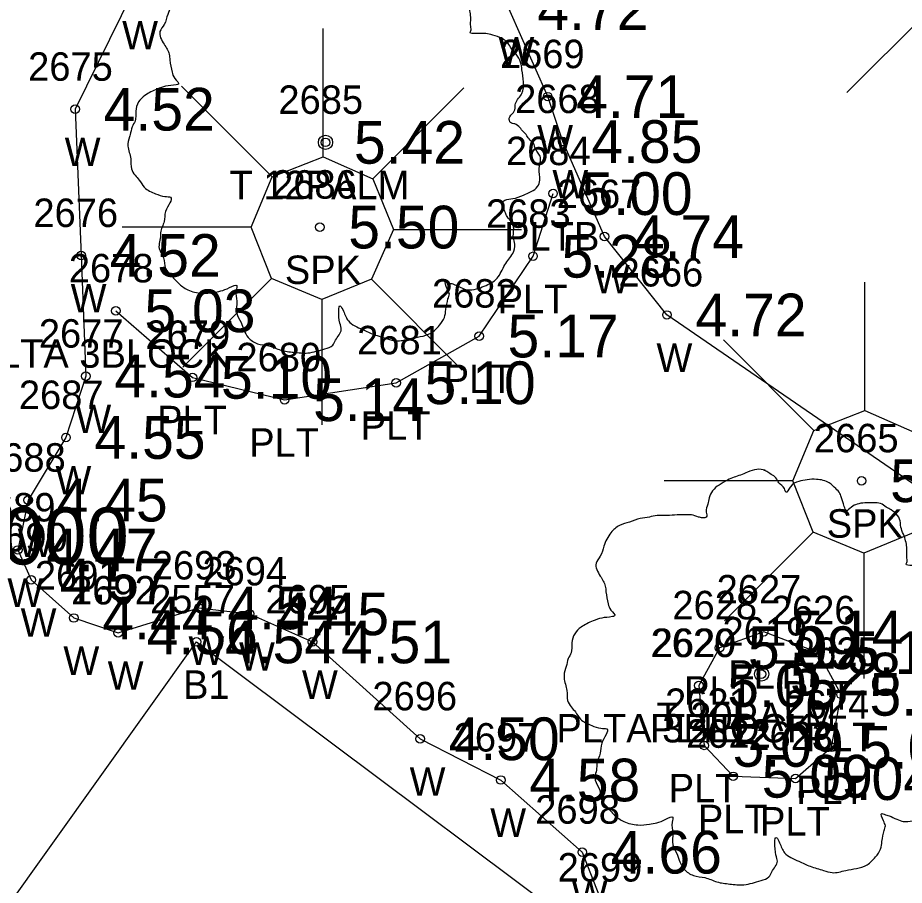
# Model space of a CAD drawing. Extents: x 2608598 to 2610682, y 641451 to 643526.
# Drawn here: x 2610088.05 to 2610119.19, y 642060.19 to 642090.67 of the extents above; entities that cross this region are included whole.
import ezdxf

# ---------------------------------------------------------------- set-up
doc = ezdxf.new("R2010")
doc.units = 0
for name, color, linetype in [('RD_EX_Bldg', 7, 'Continuous'), ('RD_EX_Bldg_txCode', 7, 'Continuous'), ('RD_EX_BldgApp', 7, 'Continuous'), ('RD_EX_BldgApp_txCode', 7, 'Continuous'), ('RD_EX_Misc_txCode', 7, 'Continuous'), ('RD_EX_TX_Bldg_ELEV', 7, 'Continuous'), ('RD_EX_TX_BldgApp_ELEV', 7, 'Continuous'), ('RD_EX_TX_Misc_ELEV', 7, 'Continuous'), ('RD_EX_TX_VEG_ELEV', 7, 'Continuous'), ('RD_EX_VEG', 7, 'Continuous'), ('RD_EX_VEG_txCode', 7, 'Continuous'), ('RD_SMD_Locator', 7, 'Continuous'), ('RD_TX_Pipe_ElevEX', 7, 'Continuous')]:
    doc.layers.add(name, color=color, linetype=linetype)

msp = doc.modelspace()

# ---------------------------------------------------------------- linework, layer by layer
at = {"layer": 'RD_EX_Bldg'}
msp.add_lwpolyline([(2610053.59, 642011.651), (2610094.327, 642068.736), (2610111.856, 642055.619), (2610105.498, 642045.99), (2610112.03, 642040.97), (2610078.047, 641993.35), (2610053.59, 642011.651)], dxfattribs=at)
at = {"layer": 'RD_EX_BldgApp'}
for p, q in [((2610120.291, 642091.155), (2610117.173, 642088.038)), ((2610098.773, 642085.777), (2610098.773, 642090.286)), ((2610096.986, 642085.079), (2610093.803, 642088.261)), ((2610100.524, 642085.007), (2610103.72, 642088.203)), ((2610096.243, 642083.315), (2610091.72, 642083.315)), ((2610101.248, 642083.233), (2610105.745, 642083.233)), ((2610096.961, 642081.503), (2610093.844, 642078.385)), ((2610100.47, 642081.478), (2610103.662, 642078.287)), ((2610117.809, 642076.863), (2610117.809, 642081.373)), ((2610098.732, 642080.771), (2610098.732, 642076.361)), ((2610116.021, 642076.165), (2610112.838, 642079.348)), ((2610115.278, 642074.401), (2610110.756, 642074.401)), ((2610115.997, 642072.589), (2610112.879, 642069.472)), ((2610117.768, 642071.858), (2610117.768, 642067.447))]:
    msp.add_line(p, q, dxfattribs=at)
for points in [[(2610092.084, 642091.554), (2610090.066, 642087.454), (2610090.275, 642082.315), (2610090.442, 642078.076), (2610089.742, 642075.92), (2610088.411, 642073.718), (2610088.053, 642071.968), (2610088.518, 642070.915), (2610090.02, 642069.577), (2610091.576, 642069.053), (2610094.413, 642069.93), (2610096.189, 642069.722), (2610098.402, 642068.736), (2610102.184, 642065.332), (2610105.016, 642063.884), (2610107.881, 642061.348), (2610108.669, 642059.316), (2610108.72, 642058.165)], [(2610119.539, 642032.985), (2610125.556, 642041.329), (2610129.153, 642046.176), (2610131.221, 642048.284), (2610137.373, 642056.194), (2610138.092, 642057.602), (2610137.208, 642060.569), (2610134.6, 642063.19), (2610131.718, 642064.679), (2610129.964, 642065.077), (2610125.881, 642067.984), (2610120.868, 642073.349), (2610110.856, 642080.224), (2610108.66, 642082.981), (2610107.198, 642086.318), (2610106.665, 642087.897), (2610105.304, 642090.989)], [(2610091.496, 642080.37), (2610094.188, 642078.032), (2610097.423, 642077.245), (2610101.34, 642077.842), (2610104.255, 642079.483), (2610106.151, 642082.287), (2610106.853, 642084.489)], [(2610111.973, 642067.204), (2610112.16, 642065.1), (2610113.185, 642064.015), (2610115.368, 642063.934), (2610116.64, 642065.037), (2610116.97, 642066.894), (2610116.18, 642068.357), (2610114.255, 642069.088), (2610112.7, 642068.531), (2610111.973, 642067.204)]]:
    msp.add_lwpolyline(points, dxfattribs=at)
for points in [[(2610096.986, 642085.079), (2610098.773, 642085.777), (2610100.524, 642085.007), (2610101.248, 642083.233), (2610100.47, 642081.478), (2610098.732, 642080.771), (2610096.961, 642081.503), (2610096.243, 642083.315)], [(2610116.021, 642076.165), (2610117.809, 642076.863), (2610119.559, 642076.094), (2610120.284, 642074.319), (2610119.506, 642072.565), (2610117.768, 642071.858), (2610115.997, 642072.589), (2610115.278, 642074.401)]]:
    msp.add_lwpolyline(points, close=True, dxfattribs=at)
at = {"layer": 'RD_EX_VEG'}
for centre, radius in [((2610098.858, 642086.29), 0.25), ((2610098.845, 642086.271), 0.0001), ((2610114.179, 642067.606), 0.25), ((2610114.166, 642067.587), 0.0001)]:
    msp.add_circle(centre, radius, dxfattribs=at)
for points in [[(2610098.989, 642093.457), (2610098.69, 642093.482), (2610098.365, 642093.382), (2610098.115, 642093.282), (2610097.89, 642093.207), (2610097.665, 642093.107), (2610097.365, 642092.933), (2610097.14, 642092.733), (2610097.015, 642092.483), (2610096.965, 642092.258), (2610096.915, 642091.983), (2610096.915, 642091.808), (2610096.79, 642091.783), (2610096.64, 642091.808), (2610096.391, 642091.883), (2610096.141, 642091.883), (2610095.891, 642091.883), (2610095.541, 642091.858), (2610095.191, 642091.858), (2610094.916, 642091.808), (2610094.591, 642091.758), (2610094.217, 642091.633), (2610093.867, 642091.508), (2610093.567, 642091.258), (2610093.317, 642090.784), (2610093.192, 642090.434), (2610093.042, 642090.184), (2610093.192, 642089.734), (2610093.367, 642089.384), (2610093.392, 642089.184), (2610093.467, 642088.759), (2610093.567, 642088.535), (2610093.692, 642088.335), (2610093.617, 642088.31), (2610093.242, 642088.26), (2610092.942, 642088.16), (2610092.517, 642087.935), (2610092.292, 642087.71), (2610092.192, 642087.385), (2610092.167, 642087.035), (2610092.068, 642086.835), (2610091.993, 642086.56), (2610091.968, 642086.485), (2610091.918, 642086.161), (2610092.018, 642085.711), (2610092.043, 642085.361), (2610092.167, 642085.136), (2610092.317, 642084.961), (2610092.492, 642084.711), (2610092.892, 642084.486), (2610093.217, 642084.386), (2610093.417, 642084.361), (2610093.242, 642083.862), (2610093.192, 642083.512), (2610093.067, 642083.112), (2610093.067, 642083.037), (2610093.017, 642082.562), (2610093.167, 642082.237), (2610093.242, 642081.862), (2610093.417, 642081.638), (2610093.692, 642081.338), (2610094.017, 642081.113), (2610094.516, 642080.988), (2610094.916, 642081.013), (2610095.491, 642081.188), (2610095.741, 642081.263), (2610095.716, 642081.088), (2610095.741, 642080.713), (2610095.741, 642080.288), (2610095.891, 642079.963), (2610095.991, 642079.688), (2610096.141, 642079.438), (2610096.466, 642079.214), (2610096.865, 642079.139), (2610097.29, 642078.989), (2610097.74, 642078.914), (2610098.24, 642078.889), (2610098.84, 642079.039), (2610099.114, 642079.164), (2610099.214, 642079.339), (2610099.414, 642079.713), (2610099.364, 642079.938), (2610099.389, 642080.538), (2610099.489, 642080.363), (2610099.664, 642080.013), (2610100.164, 642079.713), (2610100.564, 642079.538), (2610101.039, 642079.388), (2610101.338, 642079.314), (2610101.813, 642079.388), (2610102.188, 642079.463), (2610102.563, 642079.588), (2610102.863, 642079.863), (2610103.038, 642080.138), (2610103.088, 642080.413), (2610103.163, 642080.788), (2610103.213, 642080.963)], [(2610103.213, 642080.963), (2610103.138, 642081.138), (2610103.088, 642081.388), (2610103.163, 642081.363), (2610103.338, 642081.313), (2610103.612, 642081.188), (2610103.837, 642081.113), (2610104.162, 642081.138), (2610104.437, 642081.238), (2610104.887, 642081.513), (2610105.162, 642081.987), (2610105.437, 642082.387), (2610105.512, 642082.712), (2610105.462, 642082.937), (2610105.437, 642083.437), (2610105.237, 642083.687), (2610105.187, 642083.812), (2610105.087, 642084.211), (2610105.162, 642084.261), (2610105.437, 642084.311), (2610105.811, 642084.436), (2610106.086, 642084.561), (2610106.311, 642084.736), (2610106.386, 642084.961), (2610106.361, 642085.361), (2610106.411, 642085.761), (2610106.336, 642085.911), (2610106.236, 642086.061), (2610106.161, 642086.261), (2610106.011, 642086.41), (2610105.911, 642086.56), (2610105.811, 642086.66), (2610105.687, 642086.81), (2610105.512, 642086.935), (2610105.362, 642086.985), (2610105.312, 642087.135), (2610105.462, 642087.335), (2610105.512, 642087.435), (2610105.537, 642087.66), (2610105.762, 642088.01), (2610105.811, 642088.41), (2610105.762, 642088.834), (2610105.712, 642089.109), (2610105.562, 642089.384), (2610105.362, 642089.634), (2610105.237, 642089.809), (2610105.062, 642089.934), (2610104.737, 642090.059), (2610104.487, 642090.109), (2610104.137, 642090.109), (2610103.937, 642090.159), (2610103.962, 642090.209), (2610103.962, 642090.359), (2610103.962, 642090.634), (2610103.887, 642091.083), (2610103.737, 642091.583), (2610103.737, 642091.608), (2610103.637, 642091.858), (2610103.413, 642092.058), (2610103.238, 642092.158), (2610103.038, 642092.283), (2610102.788, 642092.308), (2610102.488, 642092.308), (2610102.213, 642092.258), (2610102.013, 642092.158), (2610101.838, 642092.033), (2610101.763, 642092.183), (2610101.663, 642092.483), (2610101.613, 642092.633), (2610101.463, 642092.808), (2610101.239, 642093.008), (2610100.789, 642093.132), (2610100.164, 642093.058), (2610099.864, 642092.858), (2610099.714, 642092.683), (2610099.664, 642092.808), (2610099.464, 642093.008), (2610099.364, 642093.182), (2610099.189, 642093.307), (2610099.039, 642093.407), (2610098.939, 642093.457)], [(2610114.311, 642074.773), (2610114.011, 642074.798), (2610113.686, 642074.698), (2610113.436, 642074.598), (2610113.211, 642074.523), (2610112.986, 642074.423), (2610112.686, 642074.248), (2610112.461, 642074.048), (2610112.336, 642073.799), (2610112.286, 642073.574), (2610112.237, 642073.299), (2610112.237, 642073.124), (2610112.112, 642073.099), (2610111.962, 642073.124), (2610111.712, 642073.199), (2610111.462, 642073.199), (2610111.212, 642073.199), (2610110.862, 642073.174), (2610110.512, 642073.174), (2610110.237, 642073.124), (2610109.913, 642073.074), (2610109.538, 642072.949), (2610109.188, 642072.824), (2610108.888, 642072.574), (2610108.638, 642072.099), (2610108.513, 642071.749), (2610108.363, 642071.5), (2610108.513, 642071.05), (2610108.688, 642070.7), (2610108.713, 642070.5), (2610108.788, 642070.075), (2610108.888, 642069.85), (2610109.013, 642069.65), (2610108.938, 642069.625), (2610108.563, 642069.575), (2610108.263, 642069.475), (2610107.838, 642069.251), (2610107.614, 642069.026), (2610107.514, 642068.701), (2610107.489, 642068.351), (2610107.389, 642068.151), (2610107.314, 642067.876), (2610107.289, 642067.801), (2610107.239, 642067.476), (2610107.339, 642067.026), (2610107.364, 642066.677), (2610107.489, 642066.452), (2610107.639, 642066.277), (2610107.813, 642066.027), (2610108.213, 642065.802), (2610108.538, 642065.702), (2610108.738, 642065.677), (2610108.563, 642065.177), (2610108.513, 642064.827), (2610108.388, 642064.428), (2610108.388, 642064.353), (2610108.338, 642063.878), (2610108.488, 642063.553), (2610108.563, 642063.178), (2610108.738, 642062.953), (2610109.013, 642062.653), (2610109.338, 642062.429), (2610109.838, 642062.304), (2610110.237, 642062.329), (2610110.812, 642062.503), (2610111.062, 642062.578), (2610111.037, 642062.404), (2610111.062, 642062.029), (2610111.062, 642061.604), (2610111.212, 642061.279), (2610111.312, 642061.004), (2610111.462, 642060.754), (2610111.787, 642060.529), (2610112.187, 642060.454), (2610112.611, 642060.304), (2610113.061, 642060.229), (2610113.561, 642060.204), (2610114.161, 642060.354), (2610114.436, 642060.479), (2610114.536, 642060.654), (2610114.735, 642061.029), (2610114.685, 642061.254), (2610114.71, 642061.854), (2610114.81, 642061.679), (2610114.985, 642061.329), (2610115.485, 642061.029), (2610115.885, 642060.854), (2610116.36, 642060.704), (2610116.66, 642060.629), (2610117.134, 642060.704), (2610117.509, 642060.779), (2610117.884, 642060.904), (2610118.184, 642061.179), (2610118.359, 642061.454), (2610118.409, 642061.729), (2610118.484, 642062.104), (2610118.534, 642062.279)], [(2610118.534, 642062.279), (2610118.459, 642062.454), (2610118.409, 642062.703), (2610118.484, 642062.678), (2610118.659, 642062.628), (2610118.934, 642062.503), (2610119.159, 642062.429), (2610119.483, 642062.454), (2610119.758, 642062.553), (2610120.208, 642062.828), (2610120.483, 642063.303), (2610120.758, 642063.703), (2610120.833, 642064.028), (2610120.783, 642064.253), (2610120.758, 642064.752), (2610120.558, 642065.002), (2610120.508, 642065.127), (2610120.408, 642065.527), (2610120.483, 642065.577), (2610120.758, 642065.627), (2610121.133, 642065.752), (2610121.408, 642065.877), (2610121.632, 642066.052), (2610121.707, 642066.277), (2610121.682, 642066.677), (2610121.732, 642067.076), (2610121.657, 642067.226), (2610121.557, 642067.376), (2610121.482, 642067.576), (2610121.333, 642067.726), (2610121.233, 642067.876), (2610121.133, 642067.976), (2610121.008, 642068.126), (2610120.833, 642068.251), (2610120.683, 642068.301), (2610120.633, 642068.451), (2610120.783, 642068.651), (2610120.833, 642068.751), (2610120.858, 642068.976), (2610121.083, 642069.325), (2610121.133, 642069.725), (2610121.083, 642070.15), (2610121.033, 642070.425), (2610120.883, 642070.7), (2610120.683, 642070.95), (2610120.558, 642071.125), (2610120.383, 642071.25), (2610120.058, 642071.375), (2610119.808, 642071.425), (2610119.458, 642071.425), (2610119.258, 642071.475), (2610119.283, 642071.525), (2610119.283, 642071.674), (2610119.283, 642071.949), (2610119.208, 642072.399), (2610119.059, 642072.899), (2610119.059, 642072.924), (2610118.959, 642073.174), (2610118.734, 642073.374), (2610118.559, 642073.474), (2610118.359, 642073.599), (2610118.109, 642073.624), (2610117.809, 642073.624), (2610117.534, 642073.574), (2610117.334, 642073.474), (2610117.159, 642073.349), (2610117.084, 642073.499), (2610116.984, 642073.799), (2610116.934, 642073.948), (2610116.785, 642074.123), (2610116.56, 642074.323), (2610116.11, 642074.448), (2610115.485, 642074.373), (2610115.185, 642074.173), (2610115.035, 642073.998), (2610114.985, 642074.123), (2610114.785, 642074.323), (2610114.685, 642074.498), (2610114.511, 642074.623), (2610114.361, 642074.723), (2610114.261, 642074.773)]]:
    msp.add_spline(points, degree=3, dxfattribs=at)
at = {"layer": 'RD_SMD_Locator'}
for centre in [(2610106.665, 642087.897), (2610090.066, 642087.454), (2610098.858, 642086.29), (2610107.198, 642086.318), (2610106.853, 642084.489), (2610098.659, 642083.312), (2610108.66, 642082.981), (2610090.275, 642082.315), (2610106.151, 642082.287), (2610091.496, 642080.37), (2610110.856, 642080.224), (2610104.255, 642079.483), (2610090.442, 642078.076), (2610094.188, 642078.032), (2610101.34, 642077.842), (2610097.423, 642077.245), (2610089.742, 642075.92), (2610117.695, 642074.399), (2610088.411, 642073.718), (2610088.053, 642071.968), (2610088.518, 642070.915), (2610094.413, 642069.93), (2610096.189, 642069.722), (2610090.02, 642069.577), (2610114.255, 642069.088), (2610091.576, 642069.053), (2610094.327, 642068.736), (2610098.402, 642068.736), (2610112.7, 642068.531), (2610116.18, 642068.357), (2610114.179, 642067.606), (2610111.973, 642067.204), (2610111.973, 642067.204), (2610116.97, 642066.894), (2610102.184, 642065.332), (2610112.16, 642065.1), (2610116.64, 642065.037), (2610105.016, 642063.884), (2610113.185, 642064.015), (2610115.368, 642063.934), (2610107.881, 642061.348)]:
    msp.add_circle(centre, 0.15, dxfattribs=at)

# ---------------------------------------------------------------- texts
at = {"layer": 'RD_EX_Bldg_txCode'}
for s, p in [('2557', (2610092.697, 642069.736)), ('B1', (2610093.855, 642066.736))]:
    msp.add_text(s, height=1, dxfattribs=at).set_placement(p)
at = {"layer": 'RD_EX_BldgApp_txCode'}
for s, p in [('2684', (2610105.2, 642085.489)), ('2686', (2610096.982, 642084.312)), ('2683', (2610104.497, 642083.287)), ('PLTB', (2610105.137, 642082.489)), ('2678', (2610089.842, 642081.37)), ('SPK', (2610097.431, 642081.312)), ('2682', (2610102.601, 642080.483)), ('PLT', (2610104.907, 642080.287)), ('2679', (2610092.534, 642079.032)), ('2681', (2610099.97, 642078.842)), ('PLTA 3BLOCK', (2610086.496, 642078.37)), ('2680', (2610095.73, 642078.245)), ('PLT', (2610103.011, 642077.483)), ('PLT', (2610092.943, 642076.032)), ('PLT', (2610100.096, 642075.842)), ('2665', (2610116.018, 642075.399)), ('PLT', (2610096.179, 642075.245)), ('SPK', (2610116.467, 642072.399)), ('2627', (2610112.601, 642070.088)), ('2628', (2610111.046, 642069.531)), ('2626', (2610114.503, 642069.357)), ('2620', (2610110.28, 642068.204)), ('2629', (2610110.319, 642068.204)), ('2625', (2610115.317, 642067.894)), ('PLT', (2610113.011, 642067.088)), ('PLT', (2610111.455, 642066.531)), ('PLT', (2610114.936, 642066.357)), ('2621', (2610110.79, 642066.1)), ('2624', (2610114.986, 642066.037)), ('PLTA 3BLOCK', (2610106.973, 642065.204)), ('PLTB', (2610110.256, 642065.204)), ('2622', (2610111.532, 642065.015)), ('2623', (2610113.714, 642064.934)), ('PLT', (2610115.726, 642064.894)), ('PLT', (2610110.916, 642063.1)), ('PLT', (2610115.396, 642063.037)), ('PLT', (2610111.941, 642062.015)), ('PLT', (2610114.124, 642061.934))]:
    msp.add_text(s, height=1, dxfattribs=at).set_placement(p)
at = {"layer": 'RD_EX_Misc_txCode'}
for s, p in [('W', (2610091.714, 642089.554)), ('W', (2610104.934, 642088.989)), ('2669', (2610104.988, 642088.897)), ('2675', (2610088.412, 642088.454)), ('2668', (2610105.521, 642087.318)), ('W', (2610106.295, 642085.897)), ('W', (2610089.696, 642085.454)), ('W', (2610106.828, 642084.318)), ('2667', (2610106.982, 642083.981)), ('2676', (2610088.598, 642083.315)), ('2666', (2610109.155, 642081.224)), ('W', (2610108.289, 642080.981)), ('W', (2610089.905, 642080.315)), ('2677', (2610088.789, 642079.076)), ('W', (2610110.486, 642078.224)), ('2687', (2610088.088, 642076.92)), ('W', (2610090.072, 642076.076)), ('2688', (2610086.758, 642074.718)), ('W', (2610089.372, 642073.92)), ('2689', (2610086.399, 642072.968)), ('2690', (2610086.825, 642071.915)), ('W', (2610088.041, 642071.718)), ('2693', (2610092.759, 642070.93)), ('2694', (2610094.536, 642070.722)), ('2691', (2610088.65, 642070.577)), ('W', (2610087.682, 642069.968)), ('2692', (2610089.922, 642070.053)), ('2695', (2610096.748, 642069.736)), ('W', (2610088.148, 642068.915)), ('W', (2610094.043, 642067.93)), ('W', (2610095.819, 642067.722)), ('W', (2610089.65, 642067.577)), ('W', (2610091.206, 642067.053)), ('W', (2610098.031, 642066.736)), ('2696', (2610100.507, 642066.332)), ('2697', (2610103.362, 642064.884)), ('W', (2610101.814, 642063.332)), ('2698', (2610106.228, 642062.348)), ('W', (2610104.646, 642061.884)), ('2699', (2610107.016, 642060.316)), ('W', (2610107.511, 642059.348))]:
    msp.add_text(s, height=1, dxfattribs=at).set_placement(p)
at = {"layer": 'RD_EX_TX_Bldg_ELEV'}
msp.add_text('4.54', height=1.5, dxfattribs=at).set_placement((2610095.327, 642067.986))
at = {"layer": 'RD_EX_TX_BldgApp_ELEV'}
for s, p in [('5.00', (2610107.853, 642083.739)), ('5.50', (2610099.659, 642082.562)), ('5.28', (2610107.151, 642081.537)), ('5.03', (2610092.496, 642079.62)), ('5.17', (2610105.255, 642078.733)), ('5.10', (2610095.188, 642077.282)), ('5.10', (2610102.34, 642077.092)), ('5.14', (2610098.423, 642076.495)), ('5.32', (2610118.695, 642073.649)), ('5.14', (2610115.255, 642068.338)), ('5.09', (2610113.7, 642067.781)), ('5.14', (2610117.18, 642067.607)), ('5.05', (2610112.973, 642066.454)), ('5.05', (2610112.973, 642066.454)), ('5.11', (2610117.97, 642066.144)), ('5.09', (2610113.16, 642064.35)), ('5.02', (2610117.64, 642064.287)), ('5.09', (2610114.185, 642063.265)), ('5.04', (2610116.368, 642063.184))]:
    msp.add_text(s, height=1.5, dxfattribs=at).set_placement(p)
at = {"layer": 'RD_EX_TX_Misc_ELEV'}
for s, p in [('4.72', (2610106.304, 642090.239)), ('4.71', (2610107.665, 642087.147)), ('4.52', (2610091.066, 642086.704)), ('4.85', (2610108.198, 642085.568)), ('4.74', (2610109.66, 642082.231)), ('4.52', (2610091.275, 642081.565)), ('4.72', (2610111.856, 642079.474)), ('4.54', (2610091.442, 642077.326)), ('4.55', (2610090.742, 642075.17)), ('4.45', (2610089.411, 642072.968)), ('4.47', (2610089.053, 642071.218)), ('4.57', (2610089.518, 642070.165)), ('4.54', (2610095.413, 642069.18)), ('4.45', (2610097.189, 642068.972)), ('4.44', (2610091.02, 642068.827)), ('4.56', (2610092.576, 642068.303)), ('4.51', (2610099.402, 642067.986)), ('4.50', (2610103.184, 642064.582)), ('4.58', (2610106.016, 642063.134)), ('4.66', (2610108.881, 642060.598))]:
    msp.add_text(s, height=1.5, dxfattribs=at).set_placement(p)
at = {"layer": 'RD_EX_TX_VEG_ELEV'}
for s, p in [('5.42', (2610099.858, 642085.54)), ('5.28', (2610115.179, 642066.856))]:
    msp.add_text(s, height=1.5, dxfattribs=at).set_placement(p)
at = {"layer": 'RD_EX_VEG_txCode'}
for s, p in [('2685', (2610097.204, 642087.29)), ('T 12PALM', (2610095.487, 642084.29)), ('2619', (2610112.809, 642068.606)), ('T 20PALM', (2610110.486, 642065.606))]:
    msp.add_text(s, height=1, dxfattribs=at).set_placement(p)
at = {"layer": 'RD_TX_Pipe_ElevEX'}
msp.add_text('EL=0.000', height=2, dxfattribs=at).set_placement((2610080.424, 642071.459))

doc.saveas('drawing.dxf')
